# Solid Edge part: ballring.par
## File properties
Author: KULL
Template: Iso Metric Part.par
Last saved by: KULL
Revision: 7
Application: Solid Edge
Accuracy: 0,990
Face Style: Model Default
Fill Style: Normal
Coef. of Thermal Exp: 0.0
Thermal Conductivity: 0.0
Specific Heat: 0.0
Modulus of Elasticity: 0.0
Poisson's Ratio: 0.0
Yield Stress: 0.0
Ultimate Stress: 0.0
Elongation: 0.0
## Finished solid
Body 1: sheet body, 1 face, 2 edges, 0 vertices.
  Faces by surface: cylinder 1
  Edges by curve: circle 2
Body 2: sheet body, 1 face, 2 edges, 0 vertices.
  Faces by surface: cylinder 1
  Edges by curve: circle 2
Body 3: sheet body, 1 face, 2 edges, 0 vertices.
  Faces by surface: cylinder 1
  Edges by curve: circle 2
Body 4: solid body, 272 faces, 600 edges, 320 vertices.
  Faces by surface: blend 144, torus 64, cylinder 32, plane 16, sphere 16
  Edges by curve: intersection 312, circle 288
Bounding box of the edges (mm; curved faces can reach further): 6.052 x 12.643 x 12.643, from (-1.3262, -6.3217, -6.3217) to (4.7262, 6.3217, 6.3217).
Cylindrical faces by radius (mm): R5.3033 x9, R5.5294 x8, R6.1294 x8, R6.3217 x10
Toroidal faces (ring radius, tube radius in mm): R1.2093 r0.2 x32, R5.7294 r0.2 x16, R5.9294 r0.2 x16
Spherical faces by radius (mm): R1.5 x8, R1.65 x8
Planar faces by outward normal: +x 8, -x 8
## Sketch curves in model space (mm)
arc centre (1.7, 0, 0) radius 5.8294 from (1.7, -5.1184, 2.7899) through (1.7, -2.0709, 5.4492) to (1.7, 1.6465, 5.592)
line (1.7, -1.9288, 4.6566) -> (1.7, 0, 0)
line (1.7, -5.4541, 3.1964) -> (1.7, 1.5965, 6.1168)
line (1.7, 0, 5.0783) -> (1.7, 0, 5.7)
line (1.7, 0, 6.3217) -> (1.7, 0, 5.7)
line (-3.8826, 0, 0) -> (11.2325, 0, 0)
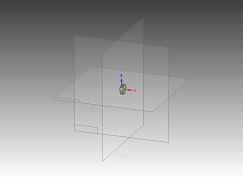
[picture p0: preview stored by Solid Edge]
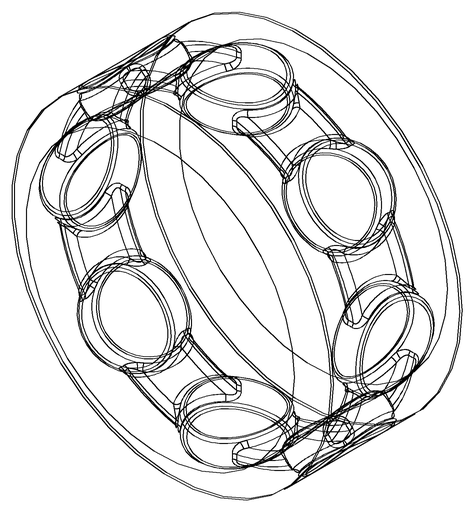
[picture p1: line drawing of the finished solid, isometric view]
